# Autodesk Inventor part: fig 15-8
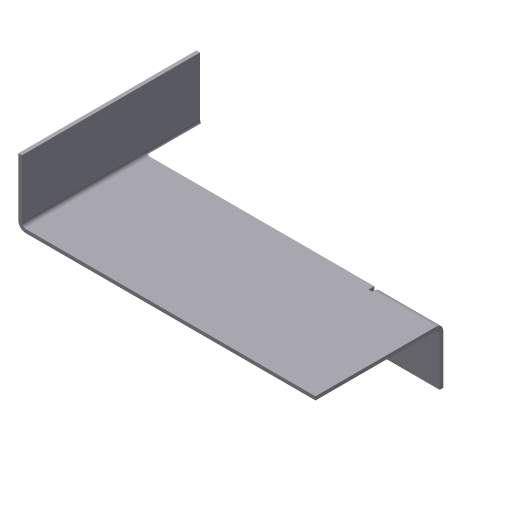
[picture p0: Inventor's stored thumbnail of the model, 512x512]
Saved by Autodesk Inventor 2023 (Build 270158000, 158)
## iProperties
Created: 2002-04
Part Number: fig 15-8
Material: Aluminum-6061
Document SubType Name: Sheet Metal
Density: 1 g/cm^3
Sheet Metal Rule: Default
Appearance: Aluminum - Flat-1
Control State: 0
Master: False
Checked Out: False
Shininess: 77.0
Angle Display Precision: 2
Document Length Units: 11269
Document Angle Units: 11279
Document Time Units: 11290
Document Mass Units: 11283
Document Length Units Precision: 3
Document Angle Units Precision: 2
Density: 0.0
Volumn: 0.0
Area: 0.0
PropertySet Name: Model Information
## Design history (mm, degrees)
node "Face1"
  sketch "Sketch1"
    geometry: L1 (-49.559, 19.574)-(-49.559, -30.426); L2 (-49.559, -30.426)-(50.441, -30.426); L3 (50.441, -30.426)-(50.441, 19.574); L4 (50.441, 19.574)-(32.941, 19.574); L5 (32.941, 19.574)-(32.941, 4.574); L6 (32.941, 4.574)-(-32.059, 4.574); L7 (-32.059, 4.574)-(-32.059, 19.574); L8 (-32.059, 19.574)-(-49.559, 19.574)
    constraints: 16 end point, 6 parallel, 2 equal length, 1 perpendicular, 1 vertical
    dimensions: "d0" = 100 distance of L1.end L2.end; "d1" = 65 distance of L5.end L6.end; "d2" = 15 distance of L6.end L7.end; "d3" = 50 distance of L1.start L1.end
sketch "Sketch2"
  geometry: L1 (100, 0)-(0, 0) reference; L2 (17.5, 50)-(17.5, 35) reference; L3 (82.5, 50)-(82.5, 0)
  constraints: 2 end point, 1 parallel, 1 point on line
sketch "Sketch3"
  geometry: L1 (81.369, -50)-(0, -50) reference; L2 (17.5, 0)-(17.5, -50)
  constraints: 2 end point, 1 perpendicular, 1 point on line
feature "Fold2" sketch "Sketch3" dims "d8" = 1 (= BendRadius), "d9" = 90 deg, "d10" = 1 (= BendRadius), "d14" = 1 (= BendReliefWidth), "d15" = 0.5 (= BendReliefDepth), "d16" = 2 (= MinimumRemnant), "d20" = 1 (= Thickness), "SeamGap" = 0.01
sketch "Sketch4"
  geometry: L1 (17.5, 0)-(17.5, -50) reference; L2 (-63.869, -15)-(0, -15) reference; L3 (0, -15)-(17.5, -15)
  constraints: 2 end point, 1 collinear, 1 point on line
feature "Fold3" sketch "Sketch4" dims "d11" = 1 (= BendRadius), "d12" = 90 deg, "d13" = 1 (= BendRadius), "d17" = 1 (= BendReliefWidth), "d18" = 0.5 (= BendReliefDepth), "d19" = 2 (= MinimumRemnant), "d20" = 1 (= Thickness), "SeamGap" = 0.01
body "Solid1"
face "Plate1" dims "d20" = 1 (= Thickness)
other parameters: "Thickness" = 1, "BendRadius" = 1 (= Thickness), "BendReliefWidth" = 1 (= Thickness), "BendReliefDepth" = 0.5 (= 0.5 x Thickness), "CornerReliefSize" = 4 (= 4 x Thickness), "MinimumRemnant" = 2 (= 2 x Thickness), "TransitionRadius" = 1 (= BendRadius), "d4" = 1 (= BendRadius), "JacobiRadiusSize" = 1 (= Thickness), "GapSize" = 1 (= Thickness)
